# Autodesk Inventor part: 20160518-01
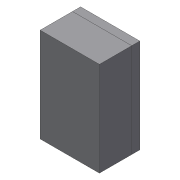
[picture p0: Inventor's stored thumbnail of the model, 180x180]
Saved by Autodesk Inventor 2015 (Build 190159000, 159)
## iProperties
Created: 2016-05
Part Number: 20160518-01
Material: Všeobecné
Document SubType Name: Modeling
Designer: navara
Density: 1 g/cm^3
Appearance: Výchozí
Author: navara
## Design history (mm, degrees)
sketch "Náčrt1"
  geometry: L1 (-7.332, -11.671)-(7.332, -11.671); L2 (7.332, -11.671)-(7.332, 11.671); L3 (7.332, 11.671)-(-7.332, 11.671); L4 (-7.332, 11.671)-(-7.332, -11.671); L5 (-7.332, -11.671)-(7.332, 11.671); L6 (7.332, -11.671)-(-7.332, 11.671); 1 further point
  constraints: 12 end point, 2 midpoint, 2 parallel, 1 horizontal, 1 perpendicular
extrude "Vysunutí1" new body sketch "Náčrt1" distance "d0" = 10; taper "d1" = 0 deg
feature "Polotovar"
feature "Sešít plochu1"
chamfer "Zkosení1" distance "d4" = 2; stored, may be unused: second distance "d5" = 2, angle "d6" = 45 deg
node "Těleso1"
node "PolotovarBody"
node "Povrch2"
